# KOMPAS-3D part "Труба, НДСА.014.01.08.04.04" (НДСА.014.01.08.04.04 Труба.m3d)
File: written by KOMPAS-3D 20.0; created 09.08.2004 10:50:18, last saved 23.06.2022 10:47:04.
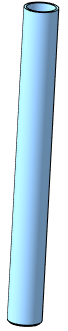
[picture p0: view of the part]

Document properties: Автор: Устинов А.В.; Организация: Эсто-вакуум; Полное имя файла: C:\Users\cherbakova\Desktop\PLM\НДСА.014.01.08.04.04 Труба.m3d

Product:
- Part/product: Труба  | designation НДСА.014.01.08.04.04
    Материал: Труба$d140х10 ГОСТ 8732-78;20 ГОСТ 8731-74$ (density 7859 kg/m3)
    Масса: 41.9469
    additional columns: <item xmlns="http://appius.ru/pdm" xmlns:xs="http://www.w3.org/2001/XMLSchema" x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; <item xmlns="http://appius.ru/pdm" xmlns:xs="http://www.w3.org/2001/XMLSchema" x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; <item xmlns="http://appius.ru/pdm" xmlns:xs="http://www.w3.org/2001/XMLSchema" x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; <item xmlns="http://appius.ru/pdm" xmlns:xs="http://www.w3.org/2001/XMLSchema" x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; <item xmlns="http://appius.ru/pdm" xmlns:xs="http://www.w3.org/2001/XMLSchema" x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; <item xmlns="http://appius.ru/pdm" xmlns:xs="http://www.w3.org/2001/XMLSchema" x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
    source file: НДСА.014.01.08.04.04 Труба.CDW

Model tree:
1. Плоскость XY
2. Плоскость ZX
3. Плоскость ZY
4. Начало координат
5. Эскиз:1
6. Операция выдавливания:1
     Расстояние 1 = 1386
7. Эскиз:2  (labels: Операция выдавливания:1; Операция выдавливания:1)
8. Вырезать элемент выдавливания:1
     Расстояние 2 = 6
9. Фаска:1  (labels: Операция выдавливания:1)
     Угол = 45; Длина 1 = 7; Длина 2 = 7
10. Эскиз:8
11. Вырезать элемент выдавливания:7
     Расстояние 1 = 76
12. Эскиз:9  (labels: Вырезать элемент выдавливания:7)
13. Вырезать элемент выдавливания:8
     Расстояние 2 = 6
14. Фаска:3  (labels: Вырезать элемент выдавливания:7; Труба$d140х10 ГОСТ 8732-78;20 ГОСТ 8731-74$)
     Угол = 45; Длина 1 = 7; Длина 2 = 7

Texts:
  НДСА.014.01.08.04.04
